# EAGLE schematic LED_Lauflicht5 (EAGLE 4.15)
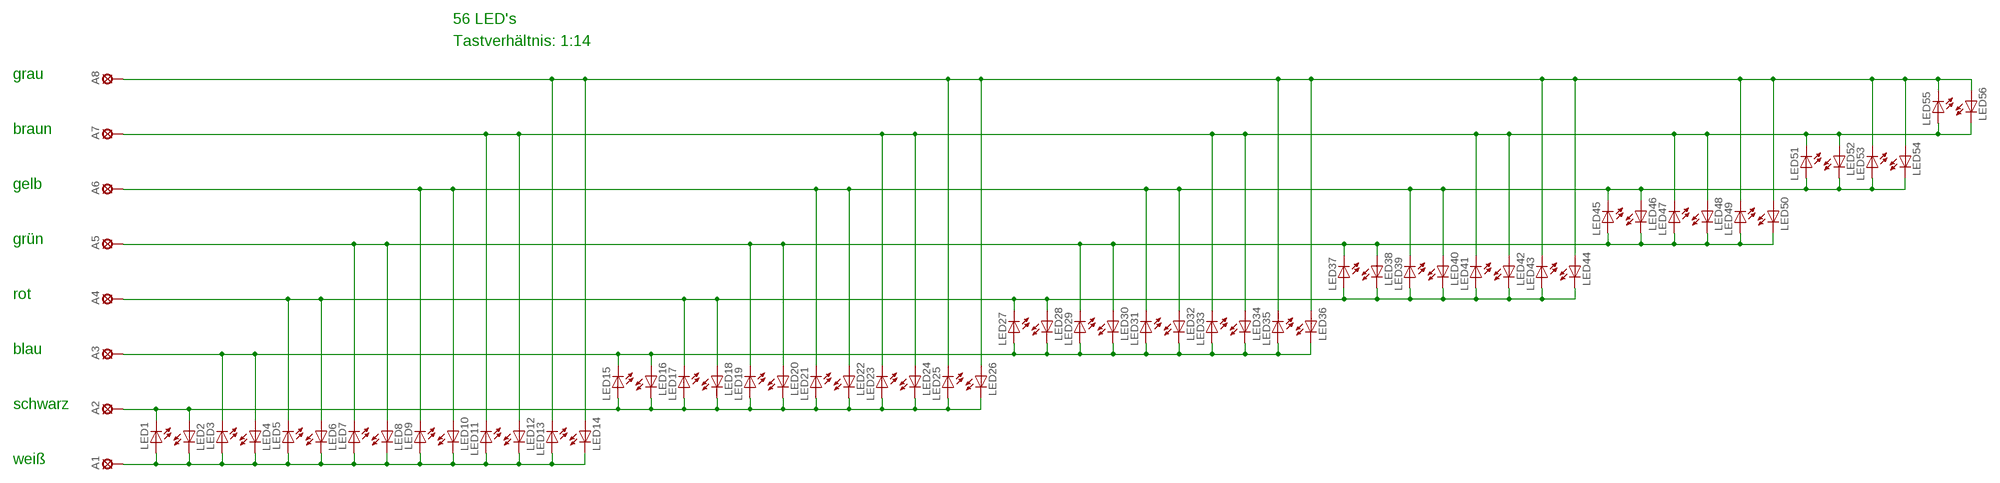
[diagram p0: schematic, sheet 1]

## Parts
A1  LSP11  [LSP11]
A2  LSP11  [LSP11]
A3  LSP11  [LSP11]
A4  LSP11  [LSP11]
A5  LSP11  [LSP11]
A6  LSP11  [LSP11]
A7  LSP11  [LSP11]
A8  LSP11  [LSP11]
LED1  LED5MM  [LED5MM]
LED2  LED5MM  [LED5MM]
LED3  LED5MM  [LED5MM]
LED4  LED5MM  [LED5MM]
LED5  LED5MM  [LED5MM]
LED6  LED5MM  [LED5MM]
LED7  LED5MM  [LED5MM]
LED8  LED5MM  [LED5MM]
LED9  LED5MM  [LED5MM]
LED10  LED5MM  [LED5MM]
LED11  LED5MM  [LED5MM]
LED12  LED5MM  [LED5MM]
LED13  LED5MM  [LED5MM]
LED14  LED5MM  [LED5MM]
LED15  LED5MM  [LED5MM]
LED16  LED5MM  [LED5MM]
LED17  LED5MM  [LED5MM]
LED18  LED5MM  [LED5MM]
LED19  LED5MM  [LED5MM]
LED20  LED5MM  [LED5MM]
LED21  LED5MM  [LED5MM]
LED22  LED5MM  [LED5MM]
LED23  LED5MM  [LED5MM]
LED24  LED5MM  [LED5MM]
LED25  LED5MM  [LED5MM]
LED26  LED5MM  [LED5MM]
LED27  LED5MM  [LED5MM]
LED28  LED5MM  [LED5MM]
LED29  LED5MM  [LED5MM]
LED30  LED5MM  [LED5MM]
LED31  LED5MM  [LED5MM]
LED32  LED5MM  [LED5MM]
LED33  LED5MM  [LED5MM]
LED34  LED5MM  [LED5MM]
LED35  LED5MM  [LED5MM]
LED36  LED5MM  [LED5MM]
LED37  LED5MM  [LED5MM]
LED38  LED5MM  [LED5MM]
LED39  LED5MM  [LED5MM]
LED40  LED5MM  [LED5MM]
LED41  LED5MM  [LED5MM]
LED42  LED5MM  [LED5MM]
LED43  LED5MM  [LED5MM]
LED44  LED5MM  [LED5MM]
LED45  LED5MM  [LED5MM]
LED46  LED5MM  [LED5MM]
LED47  LED5MM  [LED5MM]
LED48  LED5MM  [LED5MM]
LED49  LED5MM  [LED5MM]
LED50  LED5MM  [LED5MM]
LED51  LED5MM  [LED5MM]
LED52  LED5MM  [LED5MM]
LED53  LED5MM  [LED5MM]
LED54  LED5MM  [LED5MM]
LED55  LED5MM  [LED5MM]
LED56  LED5MM  [LED5MM]

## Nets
N$1: A1.MP LED1.A LED2.K(C) LED3.A LED4.K(C) LED5.A LED6.K(C) LED7.A LED8.K(C) LED9.A LED10.K(C) LED11.A LED12.K(C) LED13.A LED14.K(C)
N$2: A2.MP LED1.K(C) LED2.A LED15.A LED16.K(C) LED17.A LED18.K(C) LED19.A LED20.K(C) LED21.A LED22.K(C) LED23.A LED24.K(C) LED25.A LED26.K(C)
N$3: A3.MP LED3.K(C) LED4.A LED15.K(C) LED16.A LED27.A LED28.K(C) LED29.A LED30.K(C) LED31.A LED32.K(C) LED33.A LED34.K(C) LED35.A LED36.K(C)
N$4: A4.MP LED5.K(C) LED6.A LED17.K(C) LED18.A LED27.K(C) LED28.A LED37.A LED38.K(C) LED39.A LED40.K(C) LED41.A LED42.K(C) LED43.A LED44.K(C)
N$5: A5.MP LED7.K(C) LED8.A LED19.K(C) LED20.A LED29.K(C) LED30.A LED37.K(C) LED38.A LED45.A LED46.K(C) LED47.A LED48.K(C) LED49.A LED50.K(C)
N$6: A6.MP LED9.K(C) LED10.A LED21.K(C) LED22.A LED31.K(C) LED32.A LED39.K(C) LED40.A LED45.K(C) LED46.A LED51.A LED52.K(C) LED53.A LED54.K(C)
N$7: A7.MP LED11.K(C) LED12.A LED23.K(C) LED24.A LED33.K(C) LED34.A LED41.K(C) LED42.A LED47.K(C) LED48.A LED51.K(C) LED52.A LED55.A LED56.K(C)
N$8: A8.MP LED13.K(C) LED14.A LED25.K(C) LED26.A LED35.K(C) LED36.A LED43.K(C) LED44.A LED49.K(C) LED50.A LED53.K(C) LED54.A LED55.K(C) LED56.A

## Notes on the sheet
- 56 LED's
- Tastverhältnis: 1:14
- grau
- braun
- gelb
- grün
- rot
- blau
- schwarz
- weiß

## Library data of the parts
A1-A8 = solpad:LSP11: SOLDER PAD
LED1-LED56 = led:LED: LED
